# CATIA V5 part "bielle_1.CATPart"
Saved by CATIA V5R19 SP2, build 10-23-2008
Part number: bielle_1
Bounding box of the stored display mesh (mm): x 0 to 10, y -50 to 10, z -10 to 10
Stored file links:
  C:\Users\Guillaume\Desktop\ETUDES\IFMA\S3\IAO\Projet IAO\ggaubert_1504\bielle_1.CATPart
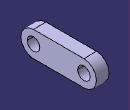
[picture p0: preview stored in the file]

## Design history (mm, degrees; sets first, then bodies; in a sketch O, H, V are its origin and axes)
Parameters
  entraxe_bielle_1 = 40 mm
Body1 (main body)
  Sketch1 on yz-plane, origin (0, 0, 0), H (0, 1, 0), V (0, 0, 1)
    line L1 (-40, 10) -> (0, 10)
    arc A1 centre (0, 0) radius 10 from (0, 10) to (0, -10) cw
    point P3 (0, 0)
    line L2 (0, -10) -> (-40, -10)
    arc A2 centre (-40, 0) radius 10 from (-40, -10) to (-40, 10) cw
    point P6 (-40, 0)
    distance L1 L2 = 20
    distance P6 P3 = 40 {= entraxe_bielle_1}
    horizontal: L1 H
    tangency: A1 L1, L2 A1, A2 L1, A2 L2
    coincidence: P3 O
  Sketch2 on yz-plane, origin (0, 0, 0), H (0, 1, 0), V (0, 0, 1)
    circle A1 centre (0, 0) radius 5
    circle A2 centre (-40, 0) radius 5
    point P1 (-40, 0)
    radius A2 = 5
    radius A1 = 5
    distance P1 O = 40 {= entraxe_bielle_1}
    coincidence: P1 H
  Pad1: profile Sketch1, direction (1, 0, 0), length 10
  Pocket1: profile Sketch2, direction (-1, 0, 0), up to end face of Pad1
